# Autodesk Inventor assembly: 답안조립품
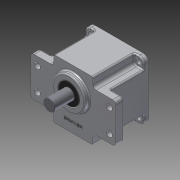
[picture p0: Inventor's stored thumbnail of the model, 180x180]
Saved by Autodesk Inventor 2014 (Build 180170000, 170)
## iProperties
Created: 2015-07
Part Number: 답안조립품
Document SubType Name: Assembly
Designer: Administrator
Author: Administrator
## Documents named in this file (12)
- C:\Users\Administrator\Desktop\450727V1005\답안조립품.iam
- C:\Users\Administrator\Desktop\450727V1005\본체.ipt
- C:\Users\Administrator\Desktop\450727V1005\커버.ipt
- C:\Users\Administrator\Desktop\450727V1005\M4x0.5x16.ipt
- C:\Users\Administrator\Desktop\450727V1005\오일실 8x22x7.ipt
- C:\Users\Administrator\Desktop\450727V1005\오일실 17x32x8.ipt
- C:\Users\Administrator\Desktop\450727V1005\베어링 6003.ipt
- 베어링 6003.ipt
- C:\Users\Administrator\Desktop\450727V1005\베어링 608.ipt
- 베어링 608.ipt
- C:\Users\Administrator\Desktop\450727V1005\메인축.ipt
- C:\Users\Administrator\Desktop\450727V1005\서브축.ipt
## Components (4 placed, 1 different names)
1. M4x0.5x12:1
2. M4x0.5x12:2
3. M4x0.5x12:3
4. M4x0.5x12:4
